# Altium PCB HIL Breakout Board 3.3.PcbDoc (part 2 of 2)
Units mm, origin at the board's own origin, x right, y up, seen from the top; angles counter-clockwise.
Board outline 262.51 x 133.53 mm, 4 copper layers (Top Layer, InternalPlane, Power, Bottom Layer); 38 components, 129 nets, 1004 pads, 22 vias.
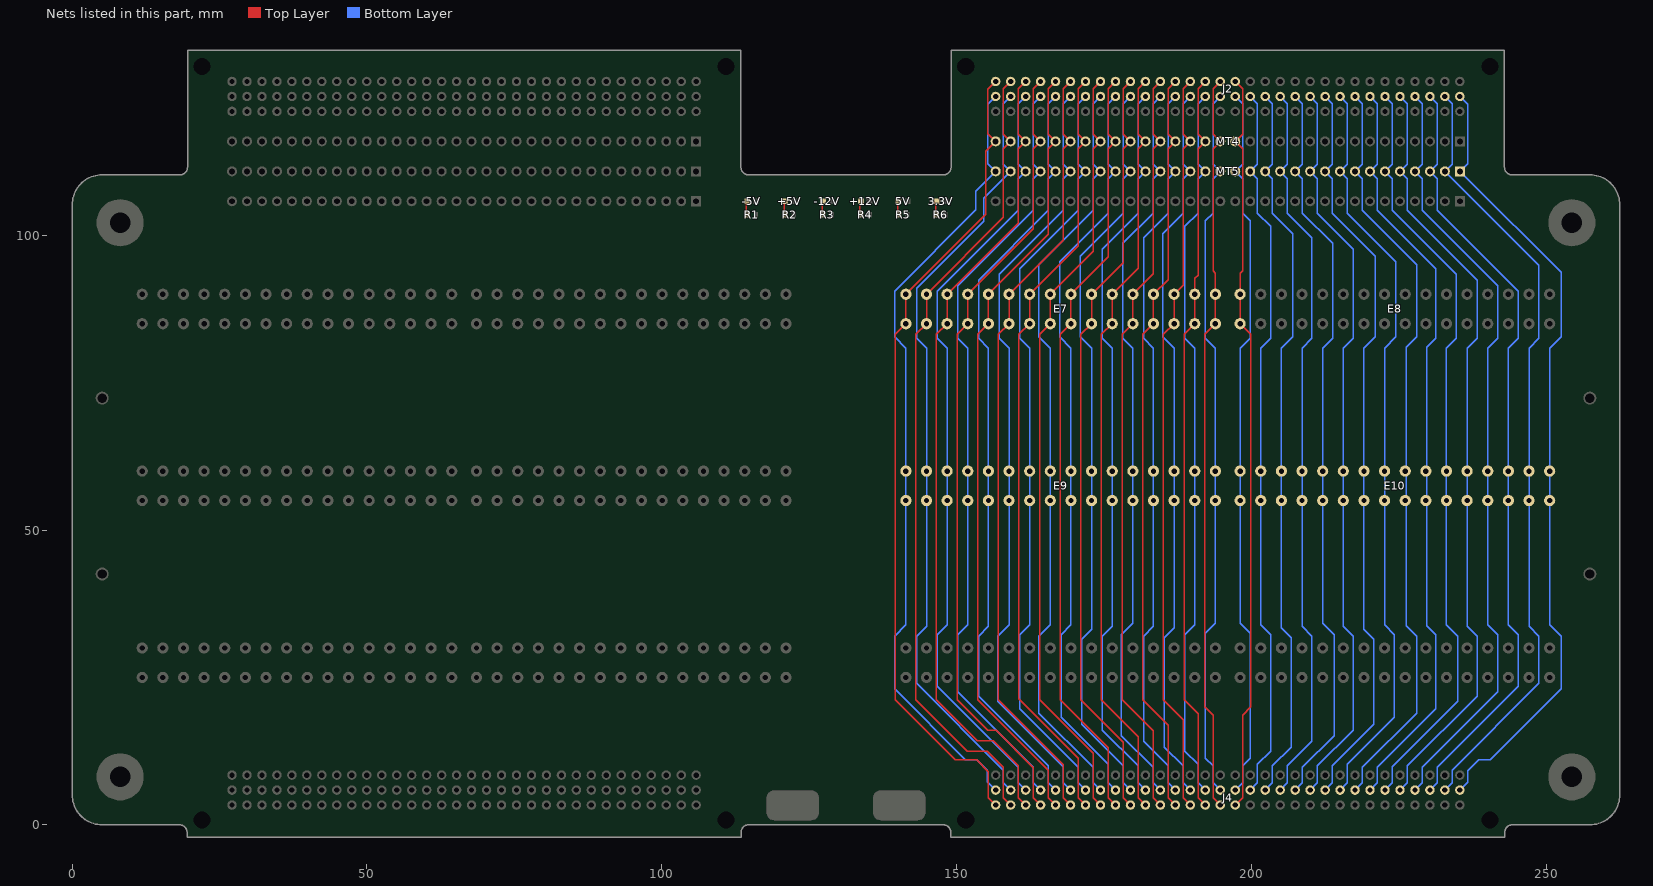
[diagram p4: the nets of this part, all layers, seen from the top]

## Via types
v1: diameter 0.6, hole 0.3, Top Layer to Bottom Layer, 12 vias
v2: diameter 1.27, hole 1, Top Layer to Bottom Layer, 10 vias

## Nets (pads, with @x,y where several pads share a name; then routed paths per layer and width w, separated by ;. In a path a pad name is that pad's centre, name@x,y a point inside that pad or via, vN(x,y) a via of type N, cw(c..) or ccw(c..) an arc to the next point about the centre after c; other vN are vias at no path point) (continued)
DI16: E8.A1 J2.A17 J4.A16 MT4.16 | length 126.3
  Top Layer w0.254: J4.A16@197.282,3.354 198.513,4.585 198.513,18.601 199.934,20.022 199.934,83.178 E8.A1@198.112,85 198.112,93.599 198.513,94 198.513,114.701 MT4.16@197.282,115.932 198.513,117.163 198.513,124.861 J2.A17@197.282,126.092
DI17: E7.A16 J2.A16 J4.A17 MT4.17 | length 126.3
  Top Layer w0.254: J4.A17@194.742,3.354 193.511,4.585 193.511,18.601 192.09,20.022 192.09,83.178 E7.A16@193.912,85 193.912,93.599 193.511,94 193.511,114.701 MT4.17@194.742,115.932 193.511,117.163 193.511,124.861 J2.A16@194.742,126.092
DI18: E7.A15 J2.A15 J4.A18 MT4.18 | length 126.8
  Top Layer w0.254: J4.A18@192.202,3.354 190.971,4.585 190.971,18.821 188.59,21.202 188.59,83.178 E7.A15@190.412,85 190.412,92.691 190.971,93.25 190.971,114.701 MT4.18@192.202,115.932 190.971,117.163 190.971,124.861 J2.A15@192.202,126.092
DI19: E7.A14 J2.A14 J4.A19 MT4.19 | length 127.5
  Top Layer w0.254: J4.A19@189.662,3.354 188.431,4.585 188.431,17.861 185.09,21.202 185.09,83.178 E7.A14@186.912,85 E7.A14@186.912,90 188.431,91.519 188.431,114.701 MT4.19@189.662,115.932 188.431,117.163 188.431,124.861 J2.A14@189.662,126.092
DI20: E7.A13 J2.A13 J4.A20 MT4.20 | length 128.3
  Top Layer w0.254: J4.A20@187.122,3.354 185.891,4.585 185.891,16.901 181.59,21.202 181.59,83.178 E7.A13@183.412,85 E7.A13@183.412,90 185.891,92.479 185.891,114.701 MT4.20@187.122,115.932 185.891,117.163 185.891,124.861 J2.A13@187.122,126.092
DI21: E7.A12 J2.A12 J4.A21 MT4.21 | length 129.1
  Top Layer w0.254: J4.A21@184.582,3.354 183.351,4.585 183.351,15.941 178.09,21.202 178.09,83.178 E7.A12@179.912,85 E7.A12@179.912,90 183.351,93.439 183.351,114.701 MT4.21@184.582,115.932 183.351,117.163 183.351,124.861 J2.A12@184.582,126.092
DI22: E7.A11 J2.A11 J4.A22 MT4.22 | length 129.9
  Top Layer w0.254: J4.A22@182.042,3.354 180.811,4.585 180.811,14.981 174.59,21.202 174.59,83.178 E7.A11@176.412,85 E7.A11@176.412,90 180.811,94.399 180.811,114.701 MT4.22@182.042,115.932 180.811,117.163 180.811,124.861 J2.A11@182.042,126.092
DI23: E7.A10 J2.A10 J4.A23 MT4.23 | length 130.7
  Top Layer w0.254: J4.A23@179.502,3.354 178.271,4.585 178.271,14.021 171.09,21.202 171.09,83.178 172.912,85 172.912,90 178.271,95.359 178.271,114.701 MT4.23@179.502,115.932 178.271,117.163 178.271,124.861 J2.A10@179.502,126.092
DI24: E7.A9 J2.A9 J4.A24 MT4.24 | length 131.5
  Top Layer w0.254: J4.A24@176.962,3.354 175.731,4.585 175.731,13.061 167.59,21.202 167.59,83.178 169.412,85 169.412,90 175.731,96.319 175.731,114.701 MT4.24@176.962,115.932 175.731,117.163 175.731,124.861 J2.A9@176.962,126.092
DI25: E7.A8 J2.A8 J4.A25 MT4.25 | length 132.3
  Top Layer w0.254: J4.A25@174.422,3.354 173.191,4.585 173.191,12.101 164.09,21.202 164.09,83.178 E7.A8@165.912,85 E7.A8@165.912,90 173.191,97.279 173.191,114.701 MT4.25@174.422,115.932 173.191,117.163 173.191,124.861 J2.A8@174.422,126.092
DI26: E7.A7 J2.A7 J4.A26 MT4.26 | length 133.1
  Top Layer w0.254: J4.A26@171.882,3.354 170.651,4.585 170.651,11.333 160.59,21.394 160.59,83.178 E7.A7@162.412,85 E7.A7@162.412,90 170.651,98.239 170.651,114.701 MT4.26@171.882,115.932 170.651,117.163 170.651,124.861 J2.A7@171.882,126.092
DI27: E7.A6 J2.A6 J4.A27 MT4.27 | length 133.9
  Top Layer w0.254: J4.A27@169.342,3.354 168.111,4.585 168.111,10.181 157.09,21.202 157.09,83.178 E7.A6@158.912,85 E7.A6@158.912,90 168.111,99.199 168.111,114.701 MT4.27@169.342,115.932 168.111,117.163 168.111,124.861 J2.A6@169.342,126.092
DI28: E7.A5 J2.A5 J4.A28 MT4.28 | length 134.7
  Top Layer w0.254: J4.A28@166.802,3.354 165.571,4.585 165.571,9.221 153.59,21.202 153.59,83.178 E7.A5@155.412,85 E7.A5@155.412,90 165.571,100.159 165.571,114.701 MT4.28@166.802,115.932 165.571,117.163 165.571,124.861 J2.A5@166.802,126.092
DI29: E7.A4 J2.A4 J4.A29 MT4.29 | length 136.3
  Top Layer w0.254: J4.A29@164.262,3.354 163.031,4.585 163.031,9.703 156.734,16 155.292,16 150.09,21.202 150.09,83.178 E7.A4@151.912,85 E7.A4@151.912,90 163.031,101.119 163.031,114.701 MT4.29@164.262,115.932 163.031,117.163 163.031,124.861 J2.A4@164.262,126.092
DI30: E7.A3 J2.A3 J4.A30 MT4.30 | length 137.9
  Top Layer w0.254: J4.A30@161.722,3.354 160.491,4.585 160.491,9.993 156.234,14.25 153.542,14.25 146.59,21.202 146.59,83.178 E7.A3@148.412,85 E7.A3@148.412,90 160.491,102.079 160.491,114.701 MT4.30@161.722,115.932 160.491,117.163 160.491,124.861 J2.A3@161.722,126.092
DI31: E7.A2 J2.A2 J4.A31 MT4.31 | length 139.1
  Top Layer w0.254: J4.A31@159.182,3.354 157.951,4.585 157.951,9.783 155.234,12.5 151.792,12.5 143.09,21.202 143.09,83.178 E7.A2@144.912,85 E7.A2@144.912,90 157.951,103.039 157.951,114.701 MT4.31@159.182,115.932 157.951,117.163 157.951,124.861 J2.A2@159.182,126.092
DI32: E7.A1 J2.A1 J4.A32 MT4.32 | length 140.1
  Top Layer w0.254: J4.A32@156.642,3.354 155.411,4.585 155.411,9.025 153.436,11 149.792,11 139.59,21.202 139.59,83.178 E7.A1@141.412,85 E7.A1@141.412,90 154.96,103.548 154.96,114.25 MT4.32@156.642,115.932 155.333,117.241 155.333,124.783 J2.A1@156.642,126.092
DO1: E10.A16 J2.B32 J4.B1 MT5.1 | length 135.7
  Bottom Layer w0.254: J4.B1@235.382,5.894 236.725,7.237 236.725,9.185 238.592,11.052 240.54,11.052 252.54,23.052 252.54,32 250.612,33.928 E10.A16@250.612,55 E10.A16@250.612,60 250.612,80.822 252.54,82.75 252.54,93.694 236.691,109.543 MT5.1@235.382,110.852 236.691,112.161 236.691,122.243 J2.B32@235.382,123.552
DO2: E10.A15 J2.B31 J4.B2 MT5.2 | length 133.3
  Bottom Layer w0.254: J4.B2@232.842,5.894 234.073,7.125 234.073,9.283 248.79,24 248.79,32 247.112,33.678 E10.A15@247.112,55 E10.A15@247.112,60 247.112,80.822 248.79,82.5 248.79,94.904 MT5.2@232.842,110.852 234.073,112.083 234.073,122.321 J2.B31@232.842,123.552
DO3: E10.A14 J2.B30 J4.B3 MT5.3 | length 132.5
  Bottom Layer w0.254: J4.B3@230.302,5.894 231.533,7.125 231.533,9.75 245.29,23.507 245.29,32.25 243.612,33.928 243.612,80.822 245.29,82.5 245.29,90.493 231.533,104.25 231.533,109.621 MT5.3@230.302,110.852 231.533,112.083 231.533,122.321 J2.B30@230.302,123.552
DO4: E10.A13 J2.B29 J4.B4 MT5.4 | length 131.7
  Bottom Layer w0.254: J4.B4@227.762,5.894 228.993,7.125 228.993,9.75 241.79,22.547 241.79,32.25 240.112,33.928 240.112,80.822 241.79,82.5 241.79,91.453 228.993,104.25 228.993,109.621 MT5.4@227.762,110.852 228.993,112.083 228.993,122.321 J2.B29@227.762,123.552
DO5: E10.A12 J2.B28 J4.B5 MT5.5 | length 130.9
  Bottom Layer w0.254: J4.B5@225.222,5.894 226.453,7.125 226.453,10 238.29,21.837 238.29,32 236.612,33.678 236.612,80.822 238.29,82.5 238.29,92.413 226.453,104.25 226.453,109.621 MT5.5@225.222,110.852 226.453,112.083 226.453,122.321 J2.B28@225.222,123.552
DO6: E10.A11 J2.B27 J4.B6 MT5.6 | length 130.3
  Bottom Layer w0.254: J4.B6@222.682,5.894 223.913,7.125 223.913,9.873 235.04,21 235.04,32 233.112,33.928 E10.A11@233.112,55 E10.A11@233.112,60 233.112,80.822 234.79,82.5 234.79,93.373 223.913,104.25 223.913,109.621 MT5.6@222.682,110.852 223.913,112.083 223.913,122.321 J2.B27@222.682,123.552
DO7: E10.A10 J2.B26 J4.B7 MT5.7 | length 129.2
  Bottom Layer w0.254: J4.B7@220.142,5.894 221.373,7.125 221.373,9.75 231.29,19.667 231.29,32.25 229.79,33.75 229.79,81 231.29,82.5 231.29,94.333 221.373,104.25 221.373,109.621 MT5.7@220.142,110.852 221.373,112.083 221.373,122.321 J2.B26@220.142,123.552
DO8: E10.A9 J2.B25 J4.B8 MT5.8 | length 128.8
  Bottom Layer w0.254: J4.B8@217.602,5.894 218.833,7.125 218.833,9.75 228.04,18.957 228.04,32 226.29,33.75 226.29,81 228.04,82.75 228.04,95.043 218.833,104.25 218.833,109.621 MT5.8@217.602,110.852 218.833,112.083 218.833,122.321 J2.B25@217.602,123.552
DO9: E10.A8 J2.B24 J4.B9 MT5.9 | length 127.9
  Bottom Layer w0.254: J4.B9@215.062,5.894 216.293,7.125 216.293,10.25 224.29,18.247 224.29,32.25 222.612,33.928 E10.A8@222.612,55 E10.A8@222.612,60 222.612,80.822 224.54,82.75 224.54,95.503 216.293,103.75 216.293,109.621 MT5.9@215.062,110.852 216.293,112.083 216.293,122.321 J2.B24@215.062,123.552
DO10: E10.A7 J2.B23 J4.B10 MT5.10 | length 127.1
  Bottom Layer w0.254: J4.B10@212.522,5.894 213.753,7.125 213.753,10 220.79,17.037 220.79,31.5 219.112,33.178 E10.A7@219.112,55 E10.A7@219.112,60 219.112,80.822 221.04,82.75 221.04,96.463 213.753,103.75 213.753,109.621 MT5.10@212.522,110.852 213.753,112.083 213.753,122.321 J2.B23@212.522,123.552
DO11: E10.A6 J2.B22 J4.B11 MT5.11 | length 126.1
  Bottom Layer w0.254: J4.B11@209.982,5.894 211.213,7.125 211.213,10 217.29,16.077 217.29,32 215.612,33.678 E10.A6@215.612,55 E10.A6@215.612,60 215.612,80.822 217.29,82.5 217.29,97.673 211.213,103.75 211.213,109.621 MT5.11@209.982,110.852 211.213,112.083 211.213,122.321 J2.B22@209.982,123.552
DO12: E10.A5 J2.B21 J4.B12 MT5.12 | length 125.5
  Bottom Layer w0.254: J4.B12@207.442,5.894 208.673,7.125 208.673,9.75 214.04,15.117 214.04,32.25 212.112,34.178 E10.A5@212.112,55 E10.A5@212.112,60 212.112,80.822 213.79,82.5 213.79,98.633 208.673,103.75 208.673,109.621 MT5.12@207.442,110.852 208.673,112.083 208.673,122.321 J2.B21@207.442,123.552
DO13: E10.A4 J2.B20 J4.B13 MT5.13 | length 124.5
  Bottom Layer w0.254: J4.B13@204.902,5.894 206.133,7.125 206.133,10 210.29,14.157 210.29,32 208.612,33.678 E10.A4@208.612,55 E10.A4@208.612,60 208.612,80.822 210.29,82.5 210.29,99.593 206.133,103.75 206.133,109.621 MT5.13@204.902,110.852 206.133,112.083 206.133,122.321 J2.B20@204.902,123.552
DO14: E10.A3 J2.B19 J4.B14 MT5.14 | length 123.9
  Bottom Layer w0.254: J4.B14@202.362,5.894 203.593,7.125 203.593,10 206.79,13.197 206.79,31.75 205.112,33.428 E10.A3@205.112,55 E10.A3@205.112,60 ; J2.B19@202.362,123.552 203.593,122.321 203.593,112.083 MT5.14@202.362,110.852 203.593,109.621 203.593,103.75 207.04,100.303 207.04,82.75 205.112,80.822 E10.A3@205.112,60
DO15: E10.A2 J2.B18 J4.B15 MT5.15 | length 122.9
  Bottom Layer w0.254: J4.B15@199.822,5.894 201.053,7.125 201.053,10.263 203.29,12.5 203.29,32.25 201.612,33.928 E10.A2@201.612,55 E10.A2@201.612,60 ; J2.B18@199.822,123.552 201.053,122.321 201.053,112.083 MT5.15@199.822,110.852 201.053,109.621 201.053,103.75 203.29,101.513 203.29,82.5 201.612,80.822 E10.A2@201.612,60
DO16: E10.A1 J2.B17 J4.B16 MT5.16 | length 122.1
  Bottom Layer w0.254: J4.B16@197.282,5.894 198.513,7.125 198.513,10 199.79,11.277 199.79,32.5 198.112,34.178 E10.A1@198.112,60 198.112,80.822 199.79,82.5 199.79,102.473 198.513,103.75 198.513,109.621 MT5.16@197.282,110.852 198.513,112.083 198.513,122.321 J2.B17@197.282,123.552
DO17: E9.A16 J2.B16 J4.B17 MT5.17 | length 122.1
  Bottom Layer w0.254: J4.B17@194.742,5.894 193.511,7.125 193.511,10 192.234,11.277 192.234,32.5 193.912,34.178 E9.A16@193.912,55 E9.A16@193.912,60 193.912,80.822 192.234,82.5 192.234,102.473 193.511,103.75 193.511,109.621 MT5.17@194.742,110.852 193.511,112.083 193.511,122.321 J2.B16@194.742,123.552
DO18: E9.A15 J2.B15 J4.B18 MT5.18 | length 122.9
  Bottom Layer w0.254: E9.A15@190.412,60 190.412,80.822 188.734,82.5 188.734,101.513 190.971,103.75 190.971,109.621 MT5.18@192.202,110.852 190.971,112.083 190.971,122.321 J2.B15@192.202,123.552 ; E9.A15@190.412,60 E9.A15@190.412,55 190.412,33.928 188.734,32.25 188.734,12.5 190.971,10.263 190.971,7.125 J4.B18@192.202,5.894
DO19: E9.A14 J2.B14 J4.B19 MT5.19 | length 123.9
  Bottom Layer w0.254: J4.B19@189.662,5.894 188.431,7.125 188.431,10 185.234,13.197 185.234,31.75 186.912,33.428 E9.A14@186.912,60 186.912,80.822 184.984,82.75 184.984,100.303 188.431,103.75 188.431,109.621 MT5.19@189.662,110.852 188.431,112.083 188.431,122.321 J2.B14@189.662,123.552
DO20: E9.A13 J2.B13 J4.B20 MT5.20 | length 124.5
  Bottom Layer w0.254: J4.B20@187.122,5.894 185.891,7.125 185.891,10 181.734,14.157 181.734,32 183.412,33.678 E9.A13@183.412,55 E9.A13@183.412,60 183.412,80.822 181.734,82.5 181.734,99.593 185.891,103.75 185.891,109.621 MT5.20@187.122,110.852 185.891,112.083 185.891,122.321 J2.B13@187.122,123.552
DO21: E9.A12 J2.B12 J4.B21 MT5.21 | length 125.5
  Bottom Layer w0.254: J4.B21@184.582,5.894 183.351,7.125 183.351,9.75 177.984,15.117 177.984,32.25 179.912,34.178 E9.A12@179.912,60 179.912,80.822 178.234,82.5 178.234,98.633 183.351,103.75 183.351,109.621 MT5.21@184.582,110.852 183.351,112.083 183.351,122.321 J2.B12@184.582,123.552
DO22: E9.A11 J2.B11 J4.B22 MT5.22 | length 126.1
  Bottom Layer w0.254: J4.B22@182.042,5.894 180.811,7.125 180.811,10 174.734,16.077 174.734,32 176.412,33.678 E9.A11@176.412,55 E9.A11@176.412,60 176.412,80.822 174.734,82.5 174.734,97.673 180.811,103.75 180.811,109.621 MT5.22@182.042,110.852 180.811,112.083 180.811,122.321 J2.B11@182.042,123.552
DO23: E9.A10 J2.B10 J4.B23 MT5.23 | length 127.1
  Bottom Layer w0.254: J4.B23@179.502,5.894 178.271,7.125 178.271,10 171.234,17.037 171.234,31.5 172.912,33.178 E9.A10@172.912,55 E9.A10@172.912,60 172.912,80.822 170.984,82.75 170.984,96.463 178.271,103.75 178.271,109.621 MT5.23@179.502,110.852 178.271,112.083 178.271,122.321 J2.B10@179.502,123.552
DO24: E9.A9 J2.B9 J4.B24 MT5.24 | length 127.9
  Bottom Layer w0.254: J4.B24@176.962,5.894 175.731,7.125 175.731,10.25 167.734,18.247 167.734,32.25 169.412,33.928 E9.A9@169.412,55 E9.A9@169.412,60 169.412,80.822 167.484,82.75 167.484,95.503 175.731,103.75 175.731,109.621 MT5.24@176.962,110.852 175.731,112.083 175.731,122.321 J2.B9@176.962,123.552
DO25: E9.A8 J2.B8 J4.B25 MT5.25 | length 128.9
  Bottom Layer w0.254: J4.B25@174.422,5.894 173.191,7.125 173.191,9.75 163.984,18.957 163.984,32 165.912,33.928 165.912,60 165.912,80.822 163.984,82.75 163.984,95.043 173.191,104.25 173.191,109.621 MT5.25@174.422,110.852 173.191,112.083 173.191,122.321 J2.B8@174.422,123.552
DO26: E9.A7 J2.B7 J4.B26 MT5.26 | length 129.3
  Bottom Layer w0.254: J4.B26@171.882,5.894 170.651,7.125 170.651,9.75 160.734,19.667 160.734,32.25 162.412,33.928 162.412,80.822 160.734,82.5 160.734,94.333 170.651,104.25 170.651,109.621 MT5.26@171.882,110.852 170.651,112.083 170.651,122.321 J2.B7@171.882,123.552
DO27: E9.A6 J2.B6 J4.B27 MT5.27 | length 130.3
  Bottom Layer w0.254: J4.B27@169.342,5.894 168.111,7.125 168.111,9.873 156.984,21 156.984,32 158.912,33.928 E9.A6@158.912,55 E9.A6@158.912,60 158.912,80.822 157.234,82.5 157.234,93.373 168.111,104.25 168.111,109.621 MT5.27@169.342,110.852 168.111,112.083 168.111,122.321 J2.B6@169.342,123.552
DO28: E9.A5 J2.B5 J4.B28 MT5.28 | length 130.9
  Bottom Layer w0.254: J4.B28@166.802,5.894 165.571,7.125 165.571,10 153.734,21.837 153.734,32 155.412,33.678 155.412,80.822 153.734,82.5 153.734,92.413 165.571,104.25 165.571,109.621 MT5.28@166.802,110.852 165.571,112.083 165.571,122.321 J2.B5@166.802,123.552
DO29: E9.A4 J2.B4 J4.B29 MT5.29 | length 131.7
  Bottom Layer w0.254: J4.B29@164.262,5.894 163.031,7.125 163.031,9.75 150.234,22.547 150.234,32.25 151.912,33.928 151.912,80.822 150.234,82.5 150.234,91.453 163.031,104.25 163.031,109.621 MT5.29@164.262,110.852 163.031,112.083 163.031,122.321 J2.B4@164.262,123.552
DO30: E9.A3 J2.B3 J4.B30 MT5.30 | length 132.5
  Bottom Layer w0.254: J4.B30@161.722,5.894 160.491,7.125 160.491,9.75 146.734,23.507 146.734,32.25 148.412,33.928 148.412,80.822 146.734,82.5 146.734,90.493 160.491,104.25 160.491,109.621 MT5.30@161.722,110.852 160.491,112.083 160.491,122.321 J2.B3@161.722,123.552
DO31: E9.A2 J2.B2 J4.B31 MT5.31 | length 133.3
  Bottom Layer w0.254: J4.B31@159.182,5.894 157.951,7.125 157.951,9.283 143.234,24 143.234,32 144.912,33.678 144.912,80.822 143.234,82.5 143.234,91 154.58,102.346 154.58,106.25 MT5.31@159.182,110.852 157.951,112.083 157.951,122.321 J2.B2@159.182,123.552
DO32: E9.A1 J2.B1 J4.B32 MT5.32 | length 135.7
  Bottom Layer w0.254: J4.B32@156.642,5.894 155.225,7.311 155.225,9.259 153.432,11.052 151.484,11.052 139.484,23.052 139.484,32 141.412,33.928 141.412,80.822 139.484,82.75 139.484,90.484 153.29,104.29 153.29,107.5 155.333,109.543 MT5.32@156.642,110.852 155.333,112.161 155.333,122.243 J2.B1@156.642,123.552
Net3.3V_1: 3.3V.1 R6.2 | length 2.4
  Top Layer w0.254: 3.3V.1@146.46,105.772 146.46,103.689 R6.2@146.649,103.5
Net5V_1: 5V.1 R5.2 | length 2.5
  Top Layer w0.254: R5.2@140.038,103.5 140.038,105.772 5V.1@140.227,105.583
Net+5V_1: +5V.1 R2.2 | length 2.5
  Top Layer w0.254: R2.2@120.772,103.5 120.772,105.772 +5V.1@120.961,105.583
Net+12V_1: +12V.1 R4.2 | length 2.5
  Top Layer w0.254: R4.2@133.616,103.5 133.616,105.772 +12V.1@133.805,105.583
Net-5V_1: -5V.1 R1.2 | length 2.5
  Top Layer w0.254: R1.2@114.35,103.5 114.35,105.772 -5V.1@114.539,105.583
Net-12V_1: -12V.1 R3.2 | length 2.5
  Top Layer w0.254: R3.2@127.194,103.5 127.194,105.772 -12V.1@127.383,105.583
pads on no net: J1. J2. J3. J4.

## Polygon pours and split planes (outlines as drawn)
15VDOUT on Power "15VDOUT_L03_P1021" (solid, pour order 1021): 157.475,52 157.475,43.5 147.975,34 144.225,34 144.225,41 146.725,43.5 146.725,52 146.725,93.25 149.975,96.5 155.225,96.5 157.475,94.25
3.3VDOUT_1 on Power "Power-No Net 1" (solid, pour order 1019): 241.79,22.547 241.79,91.628 229.337,104.325 229.337,122.682 241.225,122.682 241.225,108.5 254.225,95.5 254.225,32.25 254.225,24.358 236.725,6.858 229.337,6.858 229.337,10.094
3.3VDOUT on Power "Power-No Net" (solid, remove dead copper, pour order 1011): 228.829,10.668 241.275,23.114 241.275,90.678 228.829,103.124 228.829,122.682 198.526,122.682 198.526,6.858 228.829,6.858
5VDOUT on Power "Power-No Net" (solid, remove dead copper, pour order 1010): 160.475,43.75 147.475,30.75 147.475,24.25 150.475,21.25 157.975,21.25 160.475,18.75 160.475,6.858 193.319,6.858 193.319,122.682 160.475,122.682
+12VOUT on Power "Power-No Net" (solid, remove dead copper, pour order 1009): 56.5,127.762 84.404,127.762 84.404,1.681 56.5,1.681
-5VOUT on Power "Power-No Net" (solid, remove dead copper, pour order 1008): 56,127.762 56,1.681 28.499,1.681 28.499,127.762
-12VOUT on Bottom Layer "Power-No Net" (solid, remove dead copper, pour order 1015): 56.515,128.046 56.515,1.681 66.421,1.681 66.421,128.046
+5VOUT on Bottom Layer "Power-No Net" (solid, remove dead copper, pour order 1013): 55.88,128.046 55.88,1.681 46.101,1.681 46.101,128.046
-12VOUT on Top Layer "Power-No Net" (solid, remove dead copper, pour order 1014): 56.5,13.25 52.5,17.25 52.5,92.75 56.5,96.75 56.5,128.046 66.75,128.046 66.75,1.75 56.5,1.75
+5VOUT on Top Layer "Power-No Net" (solid, remove dead copper, pour order 1012): 56,97.116 51.75,92.866 51.75,16.962 56,12.842 56,1.75 45.75,1.75 45.75,13.25 38.25,20.75 38.25,90.453 45.75,98.095 45.75,128.046 56,128.046
AGND on InternalPlane (split plane): 112.926,111.531 112.927,111.525 112.935,111.357 112.96,111.184 113.003,111.015 113.062,110.85 113.136,110.692 113.226,110.542 113.33,110.402 113.448,110.273 113.577,110.155 113.717,110.051 113.867,109.961 114.025,109.887 114.19,109.828 114.359,109.785 114.532,109.76 114.695,109.752 114.704,109.751 114.706,109.751 137.617,109.751 137.617,102.159 130.984,95.525 130.936,95.467 130.901,95.401 130.879,95.329 130.872,95.254 130.872,0.511 114.732,0.51 114.725,0.51 114.557,0.502 114.385,0.476 114.215,0.433 114.051,0.375 113.893,0.3 113.743,0.21 113.602,0.106 113.473,-0.011 113.356,-0.141 113.252,-0.281 113.162,-0.431 113.087,-0.589 113.028,-0.753 112.986,-0.923 112.96,-1.096 112.952,-1.264 112.951,-1.27 112.951,-1.623 19.992,-1.623 19.992,-1.27 19.992,-1.264 19.983,-1.096 19.958,-0.923 19.915,-0.753 19.856,-0.589 19.782,-0.431 19.692,-0.281 19.588,-0.141 19.471,-0.011 19.341,0.106 19.201,0.21 19.051,0.3 18.893,0.375 18.729,0.433 18.559,0.476 18.386,0.502 18.218,0.51 18.212,0.51 5.08,0.51 5.062,0.509 4.781,0.518 4.483,0.547 4.188,0.596 3.897,0.664 3.61,0.751 3.33,0.856 3.058,0.98 2.794,1.121 2.54,1.279 2.297,1.453 2.066,1.643 1.847,1.847 1.643,2.066 1.453,2.297 1.279,2.54 1.121,2.794 0.98,3.058 0.856,3.33 0.751,3.61 0.664,3.897 0.596,4.188 0.547,4.483 0.518,4.781 0.509,5.062 0.51,5.08 0.51,105.139 0.515,105.186 0.513,105.204 0.522,105.485 0.552,105.782 0.6,106.077 0.668,106.368 0.755,106.654 0.86,106.934 0.984,107.206 1.125,107.47 1.282,107.723 1.457,107.966 1.646,108.197 1.85,108.416 2.069,108.62 2.3,108.809 2.543,108.984 2.796,109.141 3.06,109.282 3.332,109.406 3.612,109.511 3.898,109.598 4.189,109.666 4.484,109.714 4.781,109.744 5.062,109.753 5.08,109.751 18.288,109.751 18.294,109.752 18.462,109.76 18.635,109.785 18.805,109.828 18.969,109.887 19.127,109.961 19.277,110.051 19.417,110.155 19.547,110.273 19.664,110.402 19.768,110.542 19.858,110.692 19.933,110.85 19.991,111.015 20.034,111.184 20.06,111.357 20.068,111.525 20.068,111.531 20.068,130.884 112.926,130.884
DGND on InternalPlane (split plane): 242.441,111.531 242.441,111.525 242.449,111.357 242.475,111.184 242.518,111.015 242.576,110.85 242.651,110.692 242.741,110.542 242.845,110.402 242.962,110.273 243.092,110.155 243.232,110.051 243.382,109.961 243.54,109.887 243.704,109.828 243.874,109.785 244.047,109.76 244.215,109.752 244.221,109.751 257.429,109.751 257.447,109.753 257.728,109.744 258.026,109.714 258.321,109.665 258.612,109.598 258.899,109.511 259.179,109.405 259.451,109.282 259.715,109.141 259.969,108.983 260.212,108.809 260.443,108.619 260.662,108.414 260.866,108.196 261.056,107.965 261.23,107.721 261.388,107.467 261.529,107.204 261.653,106.931 261.758,106.651 261.845,106.365 261.913,106.073 261.962,105.778 261.991,105.48 262,105.199 261.999,105.181 261.999,5.08 262,5.062 261.991,4.781 261.962,4.483 261.913,4.188 261.845,3.897 261.758,3.61 261.653,3.33 261.529,3.058 261.388,2.794 261.23,2.54 261.056,2.297 260.866,2.066 260.662,1.847 260.443,1.643 260.212,1.453 259.969,1.279 259.715,1.121 259.451,0.98 259.179,0.856 258.899,0.751 258.612,0.664 258.321,0.596 258.026,0.547 257.728,0.518 257.447,0.509 257.429,0.51 244.272,0.51 244.265,0.51 244.097,0.502 243.925,0.476 243.755,0.433 243.591,0.375 243.433,0.3 243.283,0.21 243.142,0.106 243.013,-0.011 242.896,-0.141 242.792,-0.281 242.702,-0.431 242.627,-0.589 242.568,-0.753 242.526,-0.923 242.5,-1.096 242.492,-1.264 242.491,-1.27 242.491,-1.623 149.532,-1.623 149.532,-1.27 149.532,-1.264 149.523,-1.096 149.498,-0.923 149.455,-0.753 149.396,-0.589 149.322,-0.431 149.232,-0.281 149.128,-0.141 149.011,-0.011 148.881,0.106 148.741,0.21 148.591,0.3 148.433,0.375 148.269,0.433 148.099,0.476 147.926,0.502 147.764,0.51 147.752,0.511 131.637,0.511 131.637,95.096 138.271,101.729 138.318,101.787 138.354,101.853 138.375,101.925 138.383,102 138.383,109.751 147.803,109.751 147.809,109.752 147.977,109.76 148.15,109.785 148.319,109.828 148.484,109.887 148.642,109.961 148.792,110.051 148.932,110.155 149.061,110.273 149.179,110.402 149.283,110.542 149.373,110.692 149.447,110.85 149.506,111.015 149.549,111.184 149.574,111.357 149.582,111.525 149.583,111.531 149.583,130.884 242.441,130.884

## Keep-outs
Keep-Out Layer:
  lines w0.25: 19.482,-2.134 19.482,-1.27 ; 113.462,-2.134 113.462,-1.275 ; 149.022,-2.134 149.022,-1.27 ; 243.002,-2.134 243.002,-1.27
  lines w0.254: 0,105.186 0,5.08 ccw(c5.08,5.08) 5.08,0 18.212,0 cw(c18.212,-1.27) 19.482,-1.27 ; 0.005,105.186 cw(c5.08,105.186) 5.08,110.261 18.288,110.261 ccw(c18.288,111.531) 19.558,111.531 19.558,131.394 113.436,131.394 113.436,111.531 ccw(c114.706,111.531) 114.706,110.261 ; 19.482,-2.134 113.462,-2.134 ; 113.462,-1.27 cw(c114.732,-1.27) 114.732,0 147.752,0 cw(c147.752,-1.27) 149.022,-1.27 ; 114.704,110.261 147.803,110.261 ccw(c147.803,111.531) 149.073,111.531 149.073,131.394 242.951,131.394 242.951,111.531 ccw(c244.221,111.531) 244.221,110.261 257.429,110.261 cw(c257.429,105.181) 262.509,105.181 262.509,5.08 cw(c257.429,5.08) 257.429,0 244.272,0 ccw(c244.272,-1.27) 243.002,-1.27 ; 149.022,-2.134 243.002,-2.134

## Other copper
InternalPlane (plane layer: these items are gaps in the copper):
  lines w0.762: 131.255,0.127 131.255,95.254 138,102 138,110.266

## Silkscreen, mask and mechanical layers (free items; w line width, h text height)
Top Overlay:
  drawing of 684 lines, arcs and shapes, not listed
  text "8" at 26.721,117.348 h1.52
  text "7" at 29.324,117.348 h1.52
  text "6" at 31.864,117.348 h1.52
  text "5" at 34.373,117.348 h1.52
  text "4" at 36.913,117.348 h1.52
  text "3" at 39.484,117.348 h1.52
  text "2" at 42.037,117.348 h1.52
  text "1" at 44.628,117.348 h1.52
  text "-5V" at 47.32,117.348 h2.03
  text "+5V" at 52.146,117.348 h2.03
  text "-12V" at 56.921,117.348 h2.03
  text "+12V" at 61.798,117.348 h2.03
  text "16" at 67.056,117.348 h1.52
  text "15" at 69.596,117.348 h1.52
  text "14" at 72.161,117.348 h1.52
  text "13" at 74.676,117.348 h1.52
  text "12" at 77.241,117.348 h1.52
  text "11" at 79.807,117.348 h1.52
  text "10" at 82.347,117.348 h1.52
  text "9" at 85.204,117.348 h1.52
  text "8" at 87.744,117.348 h1.52
  text "7" at 90.284,117.348 h1.52
  text "6" at 92.824,117.348 h1.52
  text "5" at 95.364,117.348 h1.52
  text "4" at 97.904,117.348 h1.52
  text "3" at 100.444,117.348 h1.52
  text "2" at 102.984,117.348 h1.52
  text "1" at 105.524,117.348 h1.52
  text "32" at 155.956,117.348 h1.52
  text "31" at 158.496,117.348 h1.52
  text "30" at 161.036,117.348 h1.52
  text "29" at 163.576,117.348 h1.52
  text "28" at 166.116,117.348 h1.52
  text "27" at 168.656,117.348 h1.52
  text "26" at 171.196,117.348 h1.52
  text "25" at 173.736,117.348 h1.52
  text "24" at 176.276,117.348 h1.52
  text "23" at 178.816,117.348 h1.52
  text "22" at 181.356,117.348 h1.52
  text "21" at 183.896,117.348 h1.52
  text "20" at 186.436,117.348 h1.52
  text "19" at 188.976,117.348 h1.52
  text "18" at 191.516,117.348 h1.52
  text "17" at 194.056,117.348 h1.52
  text "16" at 196.596,117.348 h1.52
  text "15" at 199.136,117.348 h1.52
  text "14" at 201.676,117.348 h1.52
  text "13" at 204.216,117.348 h1.52
  text "12" at 206.756,117.348 h1.52
  text "11" at 209.296,117.348 h1.52
  text "10" at 211.836,117.348 h1.52
  text "9" at 214.694,117.348 h1.52
  text "8" at 217.233,117.348 h1.52
  text "7" at 219.773,117.348 h1.52
  text "6" at 222.314,117.348 h1.52
  text "5" at 224.853,117.348 h1.52
  text "4" at 227.393,117.348 h1.52
  text "3" at 229.933,117.348 h1.52
  text "2" at 232.474,117.348 h1.52
  text "1" at 235.013,117.348 h1.52
  text "AI" at 23.825,115.316 h2.03
  text "AO" at 107.442,115.316 h2.03
  text "DI" at 153.416,115.316 h2.03
  text "DI" at 236.982,115.189 h2.03
  text "16" at 26.391,112.268 h1.52
  text "15" at 28.986,112.268 h1.52
  text "14" at 31.537,112.268 h1.52
  text "13" at 34.044,112.268 h1.52
  text "12" at 36.601,112.268 h1.52
  text "11" at 39.231,112.268 h1.52
  text "10" at 41.711,112.268 h1.52
  text "9" at 44.507,112.268 h1.52
  text "-5V" at 47.32,112.268 h2.03
  text "+5V" at 52.146,112.268 h2.03
  text "-12V" at 56.921,112.268 h2.03
  text "+12V" at 61.798,112.268 h2.03
  text "32" at 67.056,112.268 h1.52
  text "31" at 69.673,112.268 h1.52
  text "30" at 72.157,112.268 h1.52
  text "29" at 74.663,112.268 h1.52
  text "28" at 77.224,112.268 h1.52
  text "27" at 79.715,112.268 h1.52
  text "26" at 82.333,112.268 h1.52
  text "25" at 84.912,112.268 h1.52
  text "24" at 87.457,112.268 h1.52
  text "23" at 89.99,112.268 h1.52
  text "22" at 92.54,112.268 h1.52
  text "21" at 95.155,112.268 h1.52
  text "20" at 97.63,112.268 h1.52
  text "19" at 100.199,112.268 h1.52
  text "18" at 102.744,112.268 h1.52
  text "17" at 105.163,112.268 h1.52
  text "32" at 155.956,112.268 h1.52
  text "31" at 158.496,112.268 h1.52
  text "30" at 161.036,112.268 h1.52
  text "29" at 163.576,112.268 h1.52
  text "28" at 166.116,112.268 h1.52
  text "27" at 168.656,112.268 h1.52
  text "26" at 171.196,112.268 h1.52
  text "25" at 173.736,112.268 h1.52
  text "24" at 176.276,112.268 h1.52
  text "23" at 178.816,112.268 h1.52
  text "22" at 181.356,112.268 h1.52
  text "21" at 183.896,112.268 h1.52
  text "20" at 186.436,112.268 h1.52
  text "19" at 188.976,112.268 h1.52
  text "18" at 191.516,112.268 h1.52
  text "17" at 194.056,112.268 h1.52
  text "16" at 196.596,112.268 h1.52
  text "15" at 199.136,112.268 h1.52
  text "14" at 201.676,112.268 h1.52
  text "13" at 204.216,112.268 h1.52
  text "12" at 206.756,112.268 h1.52
  text "11" at 209.296,112.268 h1.52
  text "10" at 211.836,112.268 h1.52
  text "9" at 214.694,112.268 h1.52
  text "8" at 217.233,112.268 h1.52
  text "7" at 219.773,112.268 h1.52
  text "6" at 222.314,112.268 h1.52
  text "5" at 224.853,112.268 h1.52
  text "4" at 227.393,112.268 h1.52
  text "3" at 229.933,112.268 h1.52
  text "2" at 232.474,112.268 h1.52
  text "1" at 235.013,112.268 h1.52
  text "AI" at 23.825,110.236 h2.03
  text "DO" at 152.654,110.236 h2.03
  text "DO" at 236.982,110.236 h2.03
  text "AO" at 107.442,110.211 h2.03
  text "AGND" at 63.83,102.235 h2.03
  text "DGND" at 193.446,102.216 h2.03
  text "5V" at 160.739,102.201 h2.03
  text "3.3V" at 228.506,102.201 h2.03
  text "32" at 140.015,78.164 h2.54
  text "31" at 143.615,78.164 h2.54
  text "30" at 147.015,78.164 h2.54
  text "29" at 150.515,78.164 h2.54
  text "28" at 154.015,78.164 h2.54
  text "27" at 157.515,78.164 h2.54
  text "26" at 161.015,78.164 h2.54
  text "25" at 164.515,78.164 h2.54
  text "24" at 168.015,78.164 h2.54
  text "23" at 171.515,78.164 h2.54
  text "22" at 175.015,78.164 h2.54
  text "21" at 178.515,78.164 h2.54
  text "20" at 182.015,78.164 h2.54
  text "19" at 185.515,78.164 h2.54
  text "18" at 189.015,78.164 h2.54
  text "17" at 192.515,78.164 h2.54
  text "16" at 196.815,78.164 h2.54
  text "15" at 200.315,78.164 h2.54
  text "14" at 203.815,78.164 h2.54
  text "13" at 207.315,78.164 h2.54
  text "12" at 210.815,78.164 h2.54
  text "11" at 214.315,78.164 h2.54
  text "10" at 217.815,78.164 h2.54
  text "9" at 221.815,78.164 h2.54
  text "8" at 225.315,78.164 h2.54
  text "7" at 228.815,78.164 h2.54
  text "6" at 232.315,78.164 h2.54
  text "5" at 235.815,78.164 h2.54
  text "4" at 239.315,78.164 h2.54
  text "3" at 242.815,78.164 h2.54
  text "2" at 246.315,78.164 h2.54
  text "1" at 249.815,78.164 h2.54
  text "8" at 11.075,78.139 h2.54
  text "7" at 14.575,78.139 h2.54
  text "6" at 18.075,78.139 h2.54
  text "5" at 21.575,78.139 h2.54
  text "4" at 25.075,78.139 h2.54
  text "3" at 28.575,78.139 h2.54
  text "2" at 32.075,78.139 h2.54
  text "1" at 35.575,78.139 h2.54
  text "16" at 67.275,78.139 h2.54
  text "15" at 70.775,78.139 h2.54
  text "14" at 74.275,78.139 h2.54
  text "13" at 77.775,78.139 h2.54
  text "12" at 81.275,78.139 h2.54
  text "11" at 84.775,78.139 h2.54
  text "10" at 88.275,78.139 h2.54
  text "9" at 92.275,78.139 h2.54
  text "8" at 95.775,78.139 h2.54
  text "7" at 99.275,78.139 h2.54
  text "6" at 102.775,78.139 h2.54
  text "5" at 106.275,78.139 h2.54
  text "4" at 109.775,78.139 h2.54
  text "3" at 113.275,78.139 h2.54
  text "2" at 116.775,78.139 h2.54
  text "1" at 120.275,78.139 h2.54
  text "ANALOG INPUTS" at 14.96,75.44 h2.54
  text "ANALOG OUTPUTS" at 84.418,75.44 h2.54
  text "DIGITAL INPUTS" at 187.279,75.44 h2.54
  text "-5V" at 39.573,75.413 h2.54
  text "+5V" at 46.253,75.413 h2.54
  text "-12V" at 52.807,75.413 h2.54
  text "+12V" at 59.487,75.413 h2.54
  text "AGND" at 2.54,69.088 h2.03
  text "DGND" at 254.889,69.088 h2.03
  text "16" at 10.575,48.139 h2.54
  text "15" at 14.075,48.139 h2.54
  text "14" at 17.575,48.139 h2.54
  text "13" at 21.075,48.139 h2.54
  text "12" at 24.575,48.139 h2.54
  text "11" at 28.075,48.139 h2.54
  text "10" at 31.575,48.139 h2.54
  text "9" at 35.575,48.139 h2.54
  text "32" at 67.175,48.139 h2.54
  text "31" at 70.775,48.139 h2.54
  text "30" at 74.175,48.139 h2.54
  text "29" at 77.675,48.139 h2.54
  text "28" at 81.175,48.139 h2.54
  text "27" at 84.675,48.139 h2.54
  text "26" at 88.175,48.139 h2.54
  text "25" at 91.675,48.139 h2.54
  text "24" at 95.175,48.139 h2.54
  text "23" at 98.675,48.139 h2.54
  text "22" at 102.175,48.139 h2.54
  text "21" at 105.675,48.139 h2.54
  text "20" at 109.175,48.139 h2.54
  text "19" at 112.675,48.139 h2.54
  text "18" at 116.175,48.139 h2.54
  text "17" at 119.675,48.139 h2.54
  text "32" at 140.015,48.139 h2.54
  text "31" at 143.615,48.139 h2.54
  text "30" at 147.015,48.139 h2.54
  text "29" at 150.515,48.139 h2.54
  text "28" at 154.015,48.139 h2.54
  text "27" at 157.515,48.139 h2.54
  text "26" at 161.015,48.139 h2.54
  text "25" at 164.515,48.139 h2.54
  text "24" at 168.015,48.139 h2.54
  text "23" at 171.515,48.139 h2.54
  text "22" at 175.015,48.139 h2.54
  text "21" at 178.515,48.139 h2.54
  text "20" at 182.015,48.139 h2.54
  text "19" at 185.515,48.139 h2.54
  text "18" at 189.015,48.139 h2.54
  text "17" at 192.515,48.139 h2.54
  text "16" at 196.815,48.139 h2.54
  text "15" at 200.315,48.139 h2.54
  text "14" at 203.815,48.139 h2.54
  text "13" at 207.315,48.139 h2.54
  text "12" at 210.815,48.139 h2.54
  text "11" at 214.315,48.139 h2.54
  text "10" at 217.815,48.139 h2.54
  text "9" at 221.815,48.139 h2.54
  text "8" at 225.315,48.139 h2.54
  text "7" at 228.815,48.139 h2.54
  text "6" at 232.315,48.139 h2.54
  text "5" at 235.815,48.139 h2.54
  text "4" at 239.315,48.139 h2.54
  text "3" at 242.815,48.139 h2.54
  text "2" at 246.315,48.139 h2.54
  text "1" at 249.815,48.139 h2.54
  text "ANALOG INPUTS" at 14.96,45.435 h2.54
  text "-5V" at 39.579,45.441 h2.54
  text "+5V" at 46.259,45.441 h2.54
  text "-12V" at 52.813,45.441 h2.54
  text "+12V" at 59.493,45.441 h2.54
  text "ANALOG OUTPUTS" at 84.418,45.435 h2.54
  text "DIGITAL OUTPUTS" at 185.83,45.414 h2.54
  text "AGND" at 2.54,39.243 h2.03
  text "DGND" at 254.889,39.243 h2.03
  text "3.3V" at 241.396,18.013 h2.54
  text "AGND" at 63.305,17.99 h2.54
  text "5V" at 147.198,17.988 h2.54
  text "DGND" at 192.819,17.988 h2.54
  text "Breakout Board 3.3" at 116.754,9.765 h3.81
  text "AGND" at 119.634,6.261 h2.03
  text "DGND" at 137.693,6.261 h2.03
